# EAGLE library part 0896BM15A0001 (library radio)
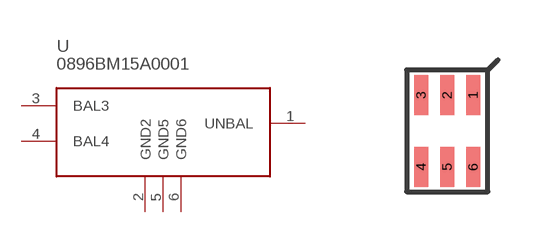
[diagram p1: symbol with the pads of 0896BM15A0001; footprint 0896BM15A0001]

Designator prefix U

## 0896BM15A0001  [0896BM15A0001]
1  UNBAL
2  GND2
3  BAL3
4  BAL4
5  GND5
6  GND6

## Footprint 0896BM15A0001 (pad centres in mm)
smd 0.35 x 1: 1 0.65,0.9; 2 0,0.9; 3 -0.65,0.9; 4 -0.65,-0.9; 5 0,-0.9; 6 0.65,-0.9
